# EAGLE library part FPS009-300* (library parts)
SD Card and MMC Reader (Manual Insertion) Source: http://www.yamaichi.de/pdf/c_fps009_3000.pdf
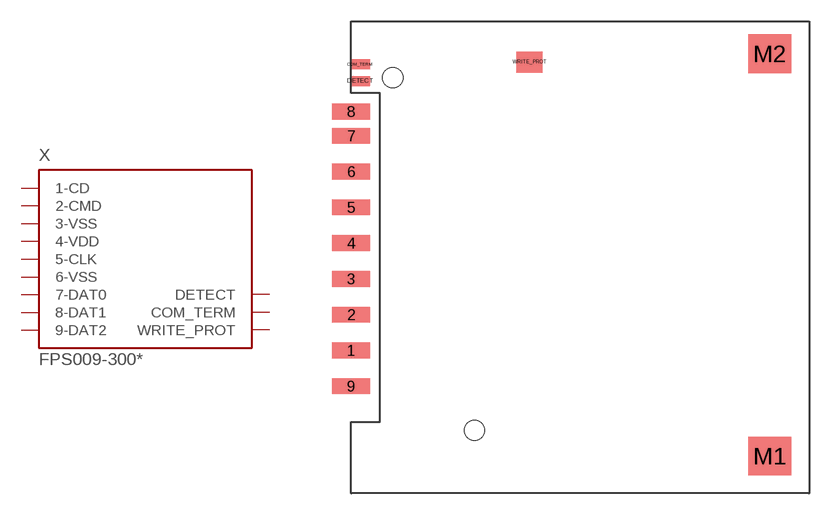
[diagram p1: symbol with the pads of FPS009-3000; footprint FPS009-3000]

Designator prefix X

## FPS009-3000 (OC_FARNELL: unknown; OC_NEWARK: unknown), FPS009-3001 (MPN: FPS009-3001-BL; OC_FARNELL: 1143952; OC_NEWARK: 91K9875), FPS009-3002 (OC_FARNELL: unknown; OC_NEWARK: unknown)  [FPS009-3000]
1  1-CD  in
2  2-CMD  in
3  3-VSS  in
4  4-VDD  in
5  5-CLK  in
6  6-VSS  in
7  7-DAT0  in
8  8-DAT1  in
9  9-DAT2  in
COM_TERM  COM_TERM  in
DETECT  DETECT  in
WRITE_PROT  WRITE_PROT  in

## Footprint FPS009-3000 (pad centres in mm)
SD Card and MMC Reader (Manual Insertion) Source: http://www.yamaichi.de/pdf/c_fps009_3000.pdf
smd 2.65 x 1.1: 1 -10,-20; 2 -10,-17.5; 3 -10,-15; 4 -10,-12.5; 5 -10,-10; 6 -10,-7.5; 7 -10,-5; 8 -10,-3.3; 9 -10,-22.5
smd 1.4 x 0.7: COM_TERM -9.396,0; DETECT -9.385,-1.159
smd 3 x 2.7: M1 19.249,-27.387; M2 19.251,0.741
smd 1.8 x 1.45: WRITE_PROT 2.464,0.152
hole 1.4 at -7.098,-0.925
hole 1.4 at -1.38,-25.585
